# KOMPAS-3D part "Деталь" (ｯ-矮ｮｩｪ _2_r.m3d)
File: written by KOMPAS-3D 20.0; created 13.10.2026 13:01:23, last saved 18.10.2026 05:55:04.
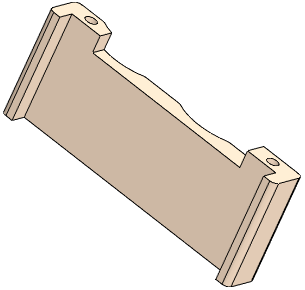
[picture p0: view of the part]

Document properties: Полное имя файла: D:\myProjects\Progect_esp32\box_compas\корпус\п-стойка_2_r.m3d

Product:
- Part/product: Деталь
    Масса: 0.0223332

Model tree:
1. Эскиз:1
2. Элемент выдавливания:1
     Расстояние 1 = 18.5
3. Эскиз:4  (with: Элемент выдавливания:1)
4. Элемент выдавливания:5
     Расстояние 2 = 18.5
5. Массив по сетке:2  (with: Элемент выдавливания:5, Эскиз:4)  (2 pattern instances)
     Шаг 1 = 10; Угол раствора = -90; Шаг 2 = 37
6. Эскиз:5  (with: Элемент выдавливания:1)
7. Элемент выдавливания:6
     Расстояние 2 = 4
8. Эскиз:8  (with: Элемент выдавливания:1)
9. Элемент выдавливания:11
     Расстояние 2 = 18.5
10. Элемент выдавливания:13  (with: Элемент выдавливания:1)
     Расстояние 1 = 1
11. Элемент выдавливания:14  (with: Элемент выдавливания:1)
     Расстояние 1 = 1
12. Эскиз:9  (with: Элемент выдавливания:1, Элемент выдавливания:13, Элемент выдавливания:14)
13. Элемент выдавливания:15
     Расстояние 2 = 3
14. Элемент выдавливания:16  (with: Элемент выдавливания:1)
     Расстояние 1 = 1
15. Элемент выдавливания:17  (with: Элемент выдавливания:1)
     Расстояние 2 = 1
16. Скругление:4  (with: Элемент выдавливания:16, Элемент выдавливания:17)
     Радиус = 1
